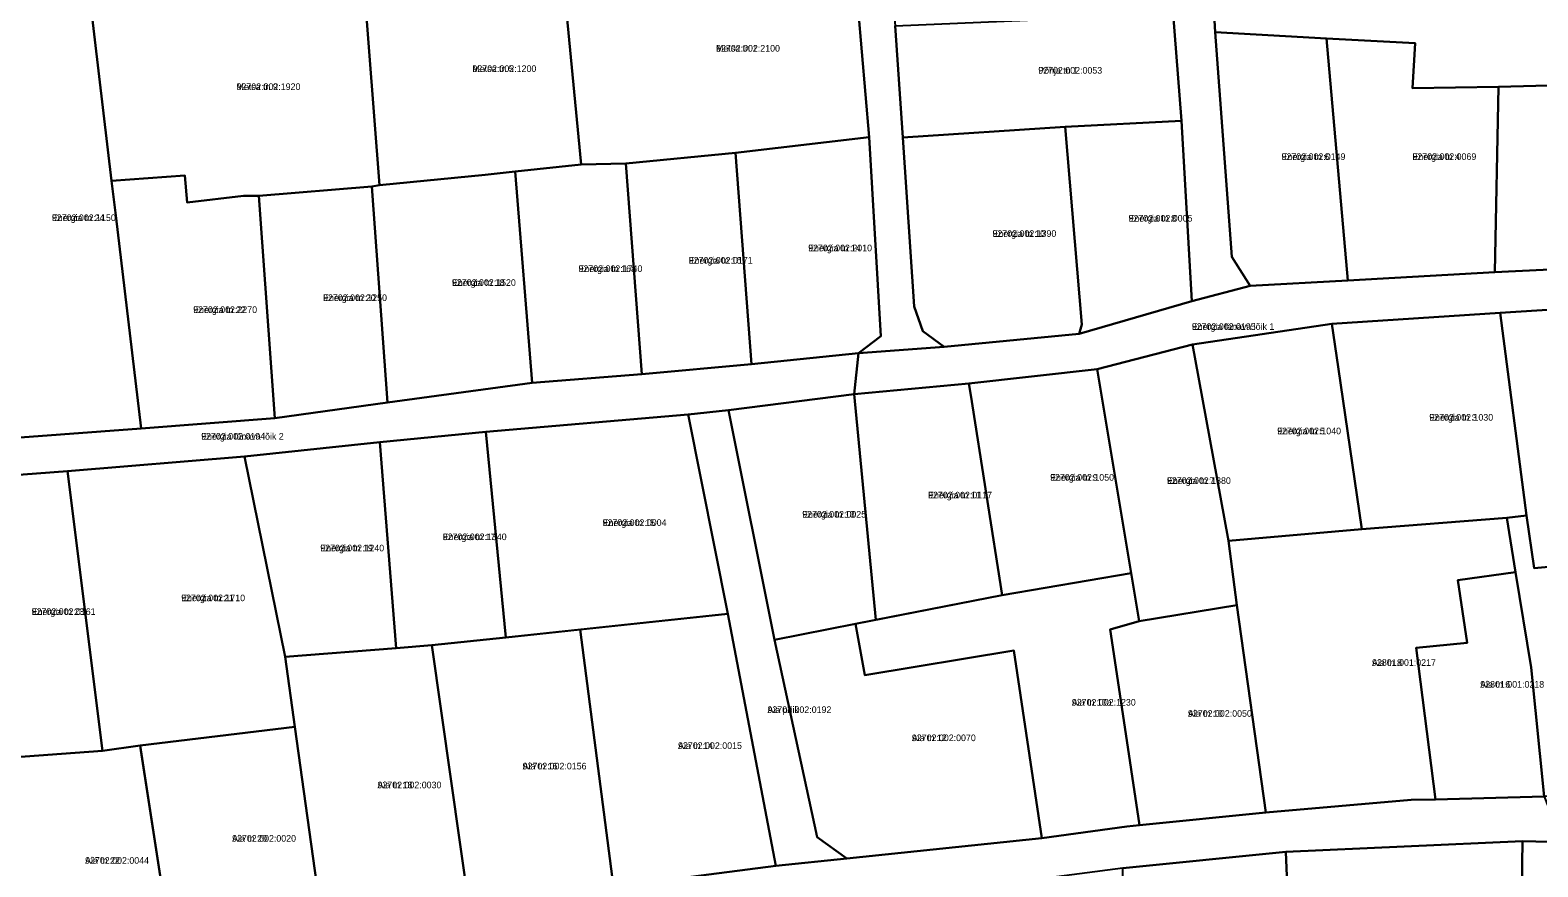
# Model space of a CAD drawing. Extents: x 615668 to 650289, y 6528908 to 6565939.
# Drawn here: x 628269.6 to 628611.8, y 6556336.2 to 6556526.3 of the extents above; entities that cross this region are included whole.
import ezdxf

# ---------------------------------------------------------------- set-up
doc = ezdxf.new("R2010")
doc.units = 0
for name, color, linetype in [('L_AADRESS', 7, 'Continuous'), ('PIIR', 7, 'Continuous'), ('TUNNUS', 7, 'Continuous')]:
    doc.layers.add(name, color=color, linetype=linetype)

msp = doc.modelspace()

# ---------------------------------------------------------------- linework, layer by layer
at = {"layer": 'PIIR'}
for points in [[(628250.61, 6556538.91), (628280.8, 6556541.24), (628310.62, 6556543.64), (628340.58, 6556546), (628370.38, 6556548.38), (628410.2, 6556551.53), (628438.14, 6556553.14), (628455.13, 6556551.95), (628464.05, 6556549.76), (628466, 6556527.24), (628467.73, 6556501.92), (628470.26, 6556463.52), (628472.26, 6556457.89), (628477.06, 6556454.38), (628457.61, 6556452.89), (628462.71, 6556456.79), (628460.03, 6556502), (628456.73, 6556540.8), (628445.77, 6556547.08), (628390.23, 6556542.26), (628345.31, 6556538.22), (628283.29, 6556532.42), (628254.3, 6556529.69)], [(628584.02, 6556523.37), (628563.85, 6556524.43), (628538.6, 6556525.86), (628537.19, 6556551.33), (628541.59, 6556551.31), (628586.03, 6556550.6), (628585.74, 6556547.93), (628589.55, 6556547.15), (628620.57, 6556541.82), (628617.06, 6556513.77), (628602.9, 6556513.42), (628583.39, 6556513.1)], [(628394.71, 6556495.76), (628390.23, 6556542.26), (628445.77, 6556547.08), (628456.73, 6556540.8), (628460.03, 6556502), (628429.7, 6556498.44), (628404.86, 6556496.01)], [(628390.23, 6556542.26), (628394.71, 6556495.76), (628379.7, 6556494.15), (628372.87, 6556493.45), (628348.95, 6556491.08), (628345.31, 6556538.22)], [(628305.26, 6556487.18), (628304.7, 6556493.28), (628288.11, 6556492.06), (628283.29, 6556532.42), (628345.31, 6556538.22), (628348.95, 6556491.08), (628347.19, 6556490.75), (628321.51, 6556488.63), (628318.07, 6556488.64)], [(628267.38, 6556433.72), (628260.2, 6556483.31), (628254.3, 6556529.69), (628283.29, 6556532.42), (628288.11, 6556492.06), (628289.05, 6556484.16), (628294.81, 6556435.83)], [(628467.73, 6556501.92), (628466, 6556527.24), (628504.89, 6556528.94), (628529.03, 6556530.89), (628530.99, 6556505.68), (628504.56, 6556504.36)], [(628538.6, 6556525.86), (628563.85, 6556524.43), (628568.74, 6556469.42), (628546.57, 6556468.2), (628542.39, 6556474.78)], [(628563.85, 6556524.43), (628584.02, 6556523.37), (628583.39, 6556513.1), (628602.9, 6556513.42), (628602.06, 6556471.29), (628568.74, 6556469.42)], [(628602.06, 6556471.29), (628602.9, 6556513.42), (628617.06, 6556513.77), (628646.6, 6556514.3), (628634.71, 6556473.89), (628631.88, 6556472.79)], [(628504.56, 6556504.36), (628508.37, 6556459.4), (628507.74, 6556457.29), (628477.06, 6556454.38), (628472.26, 6556457.89), (628470.26, 6556463.52), (628467.73, 6556501.92)], [(628507.74, 6556457.29), (628508.37, 6556459.4), (628504.56, 6556504.36), (628530.99, 6556505.68), (628533.32, 6556464.71)], [(628429.7, 6556498.44), (628460.03, 6556502), (628462.71, 6556456.79), (628457.61, 6556452.89), (628433.35, 6556450.43)], [(628404.86, 6556496.01), (628429.7, 6556498.44), (628433.35, 6556450.43), (628408.45, 6556448.14)], [(628289.05, 6556484.16), (628288.11, 6556492.06), (628304.7, 6556493.28), (628305.26, 6556487.18), (628318.07, 6556488.64), (628321.51, 6556488.63), (628325.14, 6556438.16), (628294.81, 6556435.83)], [(628347.19, 6556490.75), (628348.95, 6556491.08), (628372.87, 6556493.45), (628379.7, 6556494.15), (628383.53, 6556446.21), (628350.72, 6556441.71)], [(628379.7, 6556494.15), (628394.71, 6556495.76), (628404.86, 6556496.01), (628408.45, 6556448.14), (628383.53, 6556446.21)], [(628347.19, 6556490.75), (628350.72, 6556441.71), (628325.14, 6556438.16), (628321.51, 6556488.63)], [(628457.61, 6556452.89), (628477.06, 6556454.38), (628507.74, 6556457.29), (628533.32, 6556464.71), (628546.57, 6556468.2), (628568.74, 6556469.42), (628602.06, 6556471.29), (628631.88, 6556472.79), (628647.57, 6556470.94), (628684.8, 6556468.01), (628680.97, 6556460.49), (628633.01, 6556463.98), (628603.27, 6556462.06), (628565.09, 6556459.61), (628533.42, 6556454.87), (628511.78, 6556449.26), (628482.71, 6556446.01), (628456.66, 6556443.62)], [(628534.8, 6556447.43), (628533.42, 6556454.87), (628565.09, 6556459.61), (628566.51, 6556449.82), (628571.92, 6556412.92), (628541.6, 6556410.25)], [(628565.09, 6556459.61), (628603.27, 6556462.06), (628609.31, 6556416.04), (628604.84, 6556415.53), (628571.92, 6556412.92), (628566.51, 6556449.82)], [(628511.78, 6556449.26), (628533.42, 6556454.87), (628534.8, 6556447.43), (628541.6, 6556410.25), (628543.53, 6556395.68), (628521.37, 6556392.03), (628519.56, 6556402.96), (628512.45, 6556445.64)], [(628482.71, 6556446.01), (628511.78, 6556449.26), (628512.45, 6556445.64), (628519.56, 6556402.96), (628490.23, 6556397.96), (628483.12, 6556443.4)], [(628456.66, 6556443.62), (628482.71, 6556446.01), (628483.12, 6556443.4), (628490.23, 6556397.96), (628461.56, 6556392.37)], [(628438.59, 6556387.76), (628428.17, 6556439.95), (628456.66, 6556443.62), (628461.56, 6556392.37), (628456.96, 6556391.45)], [(628377.58, 6556388.32), (628373.05, 6556435.03), (628418.97, 6556439.01), (628427.95, 6556393.66)], [(628428.17, 6556439.95), (628438.59, 6556387.76), (628448.24, 6556342.98), (628454.99, 6556338.1), (628438.91, 6556336.43), (628427.95, 6556393.66), (628418.97, 6556439.01)], [(628352.69, 6556385.91), (628348.96, 6556432.66), (628373.05, 6556435.03), (628377.58, 6556388.32), (628360.78, 6556386.55)], [(628348.96, 6556432.66), (628352.69, 6556385.91), (628327.48, 6556383.9), (628318.26, 6556429.44)], [(628278.11, 6556426.13), (628318.26, 6556429.44), (628327.48, 6556383.9), (628329.69, 6556368.05), (628294.62, 6556363.75), (628286.06, 6556362.6)], [(628253.85, 6556424.32), (628278.11, 6556426.13), (628286.06, 6556362.6), (628262.17, 6556360.83), (628261.69, 6556361.75)], [(628543.53, 6556395.68), (628541.6, 6556410.25), (628571.92, 6556412.92), (628604.84, 6556415.53), (628606.81, 6556403.17), (628593.69, 6556401.33), (628595.83, 6556387.14), (628584.24, 6556385.99), (628588.61, 6556351.54), (628583.13, 6556351.45), (628550.07, 6556348.55)], [(628604.84, 6556415.53), (628609.31, 6556416.04), (628611.01, 6556404.05), (628642.18, 6556406.94), (628648.19, 6556353.79), (628648.4, 6556352.25), (628613.32, 6556352.2), (628610.33, 6556381.51), (628606.81, 6556403.17)], [(628492.91, 6556385.35), (628459.09, 6556379.74), (628456.96, 6556391.45), (628490.23, 6556397.96), (628519.56, 6556402.96), (628521.37, 6556392.03), (628514.8, 6556390.14), (628517.65, 6556371), (628521.42, 6556345.66), (628518.54, 6556345.4), (628499.26, 6556342.73)], [(628595.83, 6556387.14), (628593.69, 6556401.33), (628606.81, 6556403.17), (628610.33, 6556381.51), (628613.32, 6556352.2), (628588.61, 6556351.54), (628584.24, 6556385.99)], [(628402.02, 6556331.66), (628394.45, 6556390.11), (628427.95, 6556393.66), (628438.91, 6556336.43)], [(628517.65, 6556371), (628514.8, 6556390.14), (628521.37, 6556392.03), (628543.53, 6556395.68), (628550.07, 6556348.55), (628521.42, 6556345.66)], [(628456.96, 6556391.45), (628459.09, 6556379.74), (628492.91, 6556385.35), (628499.26, 6556342.73), (628454.99, 6556338.1), (628448.24, 6556342.98), (628438.59, 6556387.76)], [(628369.45, 6556325.85), (628360.78, 6556386.55), (628377.58, 6556388.32), (628394.45, 6556390.11), (628402.02, 6556331.66)], [(628369.45, 6556325.85), (628336.3, 6556320.66), (628329.69, 6556368.05), (628327.48, 6556383.9), (628352.69, 6556385.91), (628360.78, 6556386.55)], [(628336.3, 6556320.66), (628302, 6556315.55), (628294.76, 6556362.62), (628294.62, 6556363.75), (628329.69, 6556368.05)], [(628262.17, 6556360.83), (628286.06, 6556362.6), (628294.62, 6556363.75), (628302, 6556315.55), (628269.18, 6556308.92), (628263.49, 6556349.22)], [(628369.45, 6556325.85), (628402.02, 6556331.66), (628438.91, 6556336.43), (628454.99, 6556338.1), (628499.26, 6556342.73), (628518.54, 6556345.4), (628521.42, 6556345.66), (628550.07, 6556348.55), (628583.13, 6556351.45), (628588.61, 6556351.54), (628613.32, 6556352.2), (628617.38, 6556341.82), (628608.35, 6556342.06), (628554.61, 6556339.61), (628517.62, 6556335.92), (628486.41, 6556331.82), (628472.97, 6556329.99), (628431.06, 6556322.79), (628401.41, 6556320.14), (628372.17, 6556316.63)], [(628517.62, 6556335.92), (628554.61, 6556339.61), (628556.65, 6556290.09), (628532.21, 6556291.1), (628519.1, 6556291.63), (628517.65, 6556334.77)], [(628556.65, 6556290.09), (628554.61, 6556339.61), (628608.35, 6556342.06), (628607.63, 6556289.38), (628582.13, 6556289.58)], [(628617.38, 6556341.82), (628619.17, 6556299.87), (628618.82, 6556245.13), (628621.11, 6556241.84), (628607.91, 6556241.68), (628607.63, 6556289.38), (628608.35, 6556342.06)]]:
    msp.add_lwpolyline(points, close=True, dxfattribs=at)
for points in [[(628537.19, 6556551.33), (628538.6, 6556525.86), (628542.39, 6556474.78), (628546.57, 6556468.2), (628533.32, 6556464.71), (628530.99, 6556505.68), (628529.03, 6556530.89)], [(628642.18, 6556406.94), (628611.01, 6556404.05), (628609.31, 6556416.04), (628603.27, 6556462.06), (628633.01, 6556463.98)], [(628267.38, 6556433.72), (628294.81, 6556435.83), (628325.14, 6556438.16), (628350.72, 6556441.71), (628383.53, 6556446.21), (628408.45, 6556448.14), (628433.35, 6556450.43), (628457.61, 6556452.89), (628456.66, 6556443.62), (628428.17, 6556439.95), (628418.97, 6556439.01), (628373.05, 6556435.03), (628348.96, 6556432.66), (628318.26, 6556429.44), (628278.11, 6556426.13), (628253.85, 6556424.32)]]:
    msp.add_lwpolyline(points, dxfattribs=at)

# ---------------------------------------------------------------- texts
at = {"layer": 'L_AADRESS'}
for s, p in [('Metsa tn 1', (628425.31, 6556521.42)), ('Metsa tn 5', (628370.01, 6556516.8)), ('Põhja tn 1', (628498.45, 6556516.41)), ('Metsa tn 9', (628316.46, 6556512.7)), ('Energia tn 6', (628553.67, 6556496.8)), ('Energia tn 4', (628583.38, 6556496.82)), ('Energia tn 24', (628274.55, 6556482.93)), ('Energia tn 8', (628518.94, 6556482.81)), ('Energia tn 10', (628488.05, 6556479.34)), ('Energia tn 14', (628446.21, 6556476.06)), ('Energia tn 16a', (628394.08, 6556471.36)), ('Energia tn 16', (628419.11, 6556473.26)), ('Energia tn 18', (628365.36, 6556468.21)), ('Energia tn 20', (628336.11, 6556464.76)), ('Energia tn 22', (628306.62, 6556462.04)), ('Energia tänava lõik 1', (628533.3, 6556458.21)), ('Energia tn 3', (628587.2, 6556437.58)), ('Energia tänava lõik 2', (628308.44, 6556433.28)), ('Energia tn 5', (628552.67, 6556434.49)), ('Energia tn 9', (628501.14, 6556423.94)), ('Energia tn 7', (628527.66, 6556423.22)), ('Energia tn 11', (628473.44, 6556419.92)), ('Energia tn 15', (628399.56, 6556413.67)), ('Energia tn 13', (628444.87, 6556415.56)), ('Energia tn 17', (628363.27, 6556410.44)), ('Energia tn 19', (628335.47, 6556407.89)), ('Energia tn 21', (628303.9, 6556396.57)), ('Energia tn 23', (628269.96, 6556393.46)), ('Aia tn 8', (628574.21, 6556381.88)), ('Aia tn 6', (628598.78, 6556376.93)), ('Aia tn 10a', (628506.07, 6556372.85)), ('Aia põik', (628436.98, 6556371.17)), ('Aia tn 10', (628532.43, 6556370.31)), ('Aia tn 12', (628469.76, 6556364.78)), ('Aia tn 14', (628416.68, 6556363.01)), ('Aia tn 16', (628381.4, 6556358.35)), ('Aia tn 18', (628348.46, 6556354.07)), ('Aia tn 20', (628315.46, 6556341.93)), ('Aia tn 22', (628282.09, 6556336.92))]:
    msp.add_text(s, height=1.5, dxfattribs=at).set_placement(p)
at = {"layer": 'TUNNUS'}
for s, p in [('92702:002:2100', (628425.31, 6556521.42)), ('92702:002:1200', (628370.01, 6556516.8)), ('92702:002:0053', (628498.45, 6556516.41)), ('92702:002:1920', (628316.46, 6556512.7)), ('92702:002:0149', (628553.67, 6556496.8)), ('92702:002:0069', (628583.38, 6556496.82)), ('92702:002:1150', (628274.55, 6556482.93)), ('92702:002:0005', (628518.94, 6556482.81)), ('92702:002:1390', (628488.05, 6556479.34)), ('92702:002:2010', (628446.21, 6556476.06)), ('92702:002:1740', (628394.08, 6556471.36)), ('92702:002:0171', (628419.11, 6556473.26)), ('92702:002:1520', (628365.36, 6556468.21)), ('92702:002:1250', (628336.11, 6556464.76)), ('92702:002:2270', (628306.62, 6556462.04)), ('92702:002:0195', (628533.3, 6556458.21)), ('92702:002:1030', (628587.2, 6556437.58)), ('92702:002:0194', (628308.44, 6556433.28)), ('92702:002:1040', (628552.67, 6556434.49)), ('92702:002:1050', (628501.14, 6556423.94)), ('92702:002:1380', (628527.66, 6556423.22)), ('92702:002:0117', (628473.44, 6556419.92)), ('92702:002:0004', (628399.56, 6556413.67)), ('92702:002:0025', (628444.87, 6556415.56)), ('92702:002:1340', (628363.27, 6556410.44)), ('92702:002:1240', (628335.47, 6556407.89)), ('92702:002:1710', (628303.9, 6556396.57)), ('92702:002:0161', (628269.96, 6556393.46)), ('92801:001:0217', (628574.21, 6556381.88)), ('92801:001:0218', (628598.78, 6556376.93)), ('92702:002:1230', (628506.07, 6556372.85)), ('92702:002:0192', (628436.98, 6556371.17)), ('92702:002:0050', (628532.43, 6556370.31)), ('92702:002:0070', (628469.76, 6556364.78)), ('92702:002:0015', (628416.68, 6556363.01)), ('92702:002:0156', (628381.4, 6556358.35)), ('92702:002:0030', (628348.46, 6556354.07)), ('92702:002:0020', (628315.46, 6556341.93)), ('92702:002:0044', (628282.09, 6556336.92))]:
    msp.add_text(s, height=1.5, dxfattribs=at).set_placement(p)

doc.saveas('drawing.dxf')
